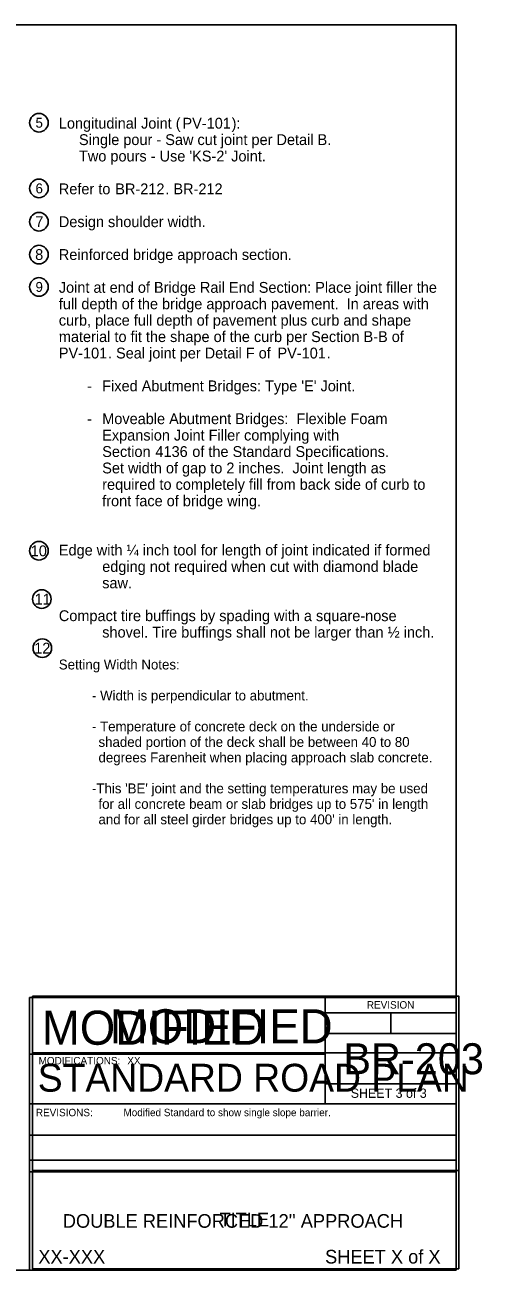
# Model space of a CAD drawing. Extents: x -2134934 to -2124557, y -2139046 to -2134021.
# Drawn here: x -2125295 to -2124557, y -2139046 to -2137036 of the extents above; entities that cross this region are included whole.
import ezdxf

# ---------------------------------------------------------------- set-up
doc = ezdxf.new("R2010")
doc.units = 0
for name, color, linetype in [('Barrier', 7, 'Continuous'), ('BridgeSuperStructureExisting', 7, 'Continuous'), ('Default', 7, 'Continuous'), ('Dimension', 7, 'Continuous'), ('dsnAlignmentCurveData', 7, 'Continuous'), ('dsnAlignmentStation', 7, 'Continuous'), ('DsnShtInsideBorder', 7, 'Continuous'), ('dsnStdLabel', 7, 'Continuous')]:
    doc.layers.add(name, color=color, linetype=linetype)

msp = doc.modelspace()

# ---------------------------------------------------------------- linework, layer by layer
at = {"layer": 'BridgeSuperStructureExisting'}
for centre in [(-2125272.5, -2137193.9), (-2125272.5, -2137299.9), (-2125272.5, -2137353.7), (-2125272.5, -2137406.7), (-2125272.5, -2137458.9), (-2125272.5, -2137884.8), (-2125267.9, -2137962.8), (-2125267, -2138042)]:
    msp.add_circle(centre, 15, dxfattribs=at)
at = {"layer": 'Dimension'}
for p, q in [((-2124810.4, -2138605.9), (-2124810.4, -2138697.3)), ((-2124810.4, -2138630.9), (-2124599.4, -2138630.9)), ((-2124704.9, -2138630.9), (-2124704.9, -2138664.1)), ((-2124810.4, -2138664.1), (-2124599.4, -2138664.1)), ((-2125287.5, -2138697.3), (-2124810.4, -2138697.3)), ((-2124810.4, -2138697.3), (-2124810.4, -2138777.3)), ((-2124599.4, -2138745.1), (-2124810.4, -2138745.1)), ((-2125287.5, -2138777.3), (-2124599.4, -2138777.3)), ((-2125287.5, -2138828.3), (-2124599.4, -2138828.3)), ((-2125287.5, -2138868.3), (-2124599.4, -2138868.3)), ((-2125287.5, -2138887.3), (-2124599.4, -2138887.3))]:
    msp.add_line(p, q, dxfattribs=at)
msp.add_lwpolyline([(-2125287.5, -2138605.9), (-2124599.4, -2138605.9), (-2124599.4, -2139045.9), (-2125287.5, -2139045.9)], close=True, dxfattribs=at)
at = {"layer": 'dsnAlignmentStation'}
msp.add_lwpolyline([(-2127734.4, -2137035.9), (-2124599.4, -2137035.9), (-2124599.4, -2139045.9), (-2127734.4, -2139045.9)], close=True, dxfattribs=at)
at = {"layer": 'DsnShtInsideBorder'}
for p, q in [((-2125283.1, -2138695), (-2124595.1, -2138695)), ((-2125283.1, -2138885), (-2124595.1, -2138885))]:
    msp.add_line(p, q, dxfattribs=at)
msp.add_lwpolyline([(-2125283.1, -2138603.7), (-2124595.1, -2138603.7), (-2124595.1, -2139043.7), (-2125283.1, -2139043.7)], close=True, dxfattribs=at)

# ---------------------------------------------------------------- texts
at = {"layer": 'Barrier'}
for s, height, p in [('5', 16, (-2125278, -2137201.9)), ('Longitudinal Joint (', 17.5, (-2125240.4, -2137203.4)), ('PV-101', 17.5, (-2125040.9, -2137203.4)), ('PV-101', 17.5, (-2125040.9, -2137203.4)), ('):', 17.5, (-2124961.6, -2137203.4)), ('     Single pour - Saw cut joint per Detail B.', 17.5, (-2125240.4, -2137229.9)), ("     Two pours - Use 'KS-2' Joint.", 17.5, (-2125240.4, -2137256.4)), ('6', 16, (-2125278, -2137307.9)), ('Refer to ', 17.5, (-2125240.4, -2137309.4)), ('BR-212', 17.5, (-2125149.3, -2137309.4)), ('.', 17.5, (-2125068.7, -2137309.4)), ('BR-212', 17.5, (-2125055.5, -2137309.4)), ('7', 17.5, (-2125278.4, -2137362.4)), ('Design shoulder width.', 17.5, (-2125240.4, -2137362.4)), ('8', 17.5, (-2125278.6, -2137415.4)), ('Reinforced bridge approach section.', 17.5, (-2125240.4, -2137415.4)), ('9', 16, (-2125278, -2137466.9)), ('Joint at end of Bridge Rail End Section: Place joint filler the ', 17.5, (-2125240.4, -2137468.4)), ('full depth of the bridge approach pavement.  In areas with ', 17.5, (-2125240.4, -2137494.9)), ('curb, place full depth of pavement plus curb and shape ', 17.5, (-2125240.4, -2137521.4)), ('material to fit the shape of the curb per Section B-B of', 17.5, (-2125240.4, -2137547.9)), ('PV-101', 17.5, (-2125240.4, -2137574.4)), ('PV-101', 17.5, (-2125240.4, -2137574.4)), ('. Seal joint per Detail F of ', 17.5, (-2125161.1, -2137574.4)), ('PV-101', 17.5, (-2124887.6, -2137574.4)), ('PV-101', 17.5, (-2124887.6, -2137574.4)), ('.', 17.5, (-2124808.4, -2137574.4)), ("Fixed Abutment Bridges: Type 'E' Joint.", 17.5, (-2125170.4, -2137627.4)), ('       -', 17.5, (-2125240.4, -2137627.4)), ('Moveable Abutment Bridges:  Flexible Foam', 17.5, (-2125170.4, -2137680.4)), ('       -', 17.5, (-2125240.4, -2137680.4)), ('Expansion Joint Filler complying with ', 17.5, (-2125170.4, -2137706.9)), ('Section ', 17.5, (-2125170.4, -2137733.4)), ('4136', 17.5, (-2125084.5, -2137733.4)), ('4136', 17.5, (-2125084.5, -2137733.4)), (' of the Standard Specifications.', 17.5, (-2125031.6, -2137733.4)), ('Set width of gap to 2 inches.  Joint length as ', 17.5, (-2125170.4, -2137759.9)), ('required to completely fill from back side of curb to ', 17.5, (-2125170.4, -2137786.4)), ('front face of bridge wing.', 17.5, (-2125170.4, -2137812.9)), ('Edge with ¼ inch tool for length of joint indicated if formed ', 17.5, (-2125240.4, -2137892.4)), ('edging not required when cut with diamond blade ', 17.5, (-2125170.4, -2137918.9)), ('saw.', 17.5, (-2125170.4, -2137945.4)), ('Compact tire buffings by spading with a square-nose ', 17.5, (-2125240.4, -2137998.4)), ('shovel. Tire buffings shall not be larger than ½ inch.', 17.5, (-2125170.4, -2138024.9)), ('Setting Width Notes:', 16, (-2125240.4, -2138076.4)), ('         - Width is perpendicular to abutment.', 16, (-2125240.4, -2138126.4)), ('         - Temperature of concrete deck on the underside or ', 16, (-2125240.4, -2138176.4)), ('shaded portion of the deck shall be between 40 to 80 ', 16, (-2125176.4, -2138201.4)), ('degrees Farenheit when placing approach slab concrete.', 16, (-2125176.4, -2138226.4)), ("         -This 'BE' joint and the setting temperatures may be used ", 16, (-2125240.4, -2138276.4)), ("for all concrete beam or slab bridges up to 575' in length ", 16, (-2125176.4, -2138301.4)), ("and for all steel girder bridges up to 400' in length.", 16, (-2125176.4, -2138326.4))]:
    msp.add_text(s, height=height, dxfattribs=at).set_placement(p)
at = {"layer": 'Default'}
msp.add_text('MODIFIED', height=55, dxfattribs=at).set_placement((-2125267.8, -2138682.2))
at = {"layer": 'Dimension'}
for s, height, p in [('REVISION', 12, (-2124743.4, -2138623.8)), ('BR-203', 50, (-2124781.2, -2138729.8)), ('STANDARD ROAD PLAN', 45.001, (-2125274.4, -2138757.9)), ('SHEET 3 of 3', 15, (-2124769.4, -2138767.9)), ('Modified Standard to show single slope barrier.', 12, (-2125136.1, -2138797.5)), ("DOUBLE REINFORCED 12'' APPROACH", 22, (-2125234, -2138977.6))]:
    msp.add_text(s, height=height, dxfattribs=at).set_placement(p)
at = {"layer": 'dsnAlignmentCurveData'}
msp.add_text('REVISIONS:', height=12, dxfattribs=at).set_placement((-2125277.5, -2138797.6))
at = {"layer": 'DsnShtInsideBorder'}
for s, height, p in [('MODIFIED', 55, (-2125158.1, -2138679.9)), ('MODIFICATIONS:', 12, (-2125273.1, -2138713.9)), ('XX', 12, (-2125129.9, -2138713.9)), ('TITLE', 22, (-2124981.1, -2138975.4)), ('XX-XXX', 22, (-2125273.5, -2139035.3)), ('SHEET X of X', 22, (-2124810.8, -2139035.3))]:
    msp.add_text(s, height=height, dxfattribs=at).set_placement(p)
at = {"layer": 'dsnStdLabel'}
for s, p in [('10', (-2125285.7, -2137893.7)), ('11', (-2125279.5, -2137971.7)), ('12', (-2125280.1, -2138050.8))]:
    msp.add_text(s, height=17.5, dxfattribs=at).set_placement(p)

doc.saveas('drawing.dxf')
